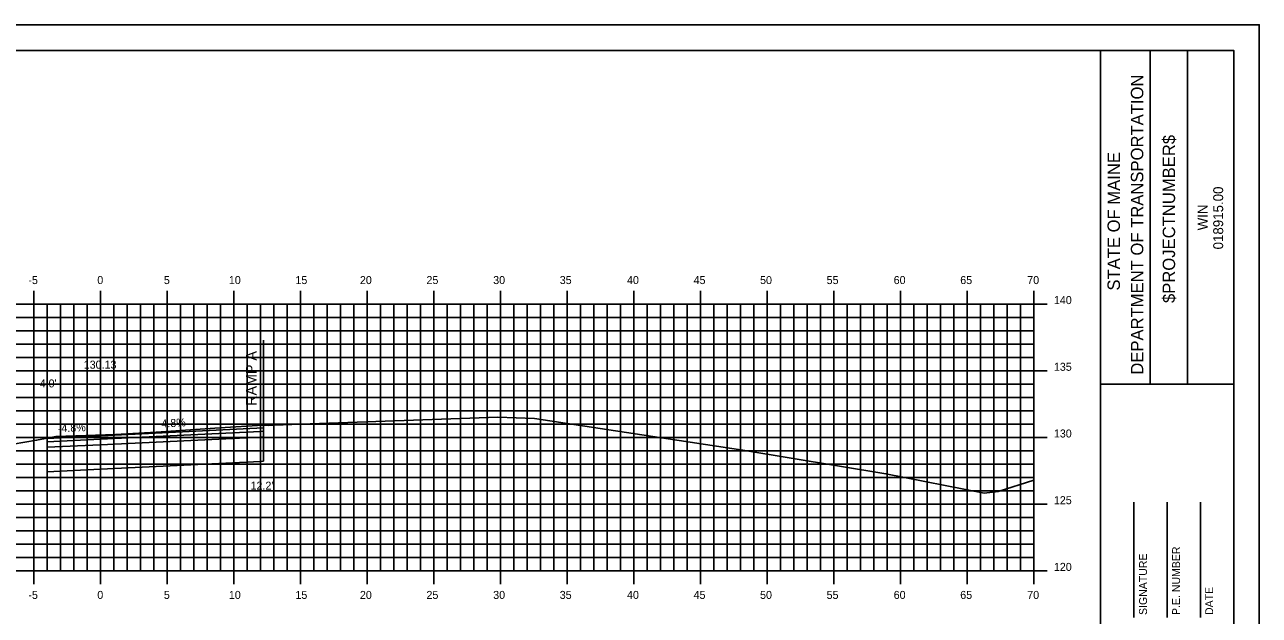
# Model space of a CAD drawing. Extents: x 850851 to 851023, y 365624 to 365734.
# Drawn here: x 850928.8 to 851021.4, y 365689.7 to 365734 of the extents above; entities that cross this region are included whole.
import ezdxf

# ---------------------------------------------------------------- set-up
doc = ezdxf.new("R2010")
doc.units = 0
for name, color, linetype in [('ANNOTATION', 7, 'Continuous'), ('BORDER', 7, 'Continuous'), ('D_Roadway_Centerline', 7, 'Continuous'), ('D_Roadway_Centerline_Text', 7, 'Continuous'), ('D_Roadway_Edge_Shoulder', 7, 'Continuous'), ('D_Roadway_Pavement', 7, 'Continuous'), ('D_Roadway_SubGrade', 7, 'Continuous'), ('D_Text_Standard', 7, 'Continuous'), ('H_V ANNOTATION', 7, 'Continuous'), ('M_Roadway_Centerline', 7, 'Continuous'), ('MAJOR', 7, 'Continuous'), ('MINOR', 7, 'Continuous'), ('PLOT BOUNDARY', 7, 'Continuous'), ('S_Roadway_Centerline', 7, 'Continuous')]:
    doc.layers.add(name, color=color, linetype=linetype)

msp = doc.modelspace()

# ---------------------------------------------------------------- linework, layer by layer
at = {"layer": 'BORDER'}
for p, q in [((851009.496, 365627.027), (851009.496, 365732.027)), ((851013.225, 365707.024), (851013.225, 365732.024)), ((851016.02, 365707.024), (851016.02, 365732.024)), ((851009.497, 365707.021), (851019.496, 365707.021)), ((851011.996, 365689.53), (851011.996, 365698.177)), ((851014.496, 365689.53), (851014.496, 365698.177)), ((851016.996, 365689.53), (851016.996, 365698.177))]:
    msp.add_line(p, q, dxfattribs=at)
msp.add_lwpolyline([(850859.496, 365627.027), (851019.496, 365627.027), (851019.496, 365732.027), (850859.496, 365732.027)], close=True, dxfattribs=at)
at = {"layer": 'D_Roadway_Edge_Shoulder'}
for p, q in [((850946.708, 365703.74), (850930.496, 365702.962)), ((850946.496, 365703.73), (850946.496, 365703.48)), ((850934.494, 365702.904), (850934.496, 365703.154))]:
    msp.add_line(p, q, dxfattribs=at)
at = {"layer": 'D_Roadway_Pavement'}
for points in [[(850934.494, 365702.904), (850930.494, 365702.712), (850930.494, 365702.295), (850934.494, 365702.487)], [(850934.494, 365702.904), (850946.494, 365703.48), (850946.494, 365703.063), (850934.494, 365702.487)]]:
    msp.add_lwpolyline(points, close=True, dxfattribs=at)
msp.add_lwpolyline([(850946.708, 365703.073), (850946.494, 365703.063), (850946.494, 365703.48), (850946.708, 365703.49)], dxfattribs=at)
at = {"layer": 'D_Roadway_SubGrade'}
for p, q in [((850946.708, 365710.321), (850946.708, 365703.574)), ((850946.708, 365703.574), (850946.708, 365701.24))]:
    msp.add_line(p, q, dxfattribs=at)
for points in [[(850934.494, 365702.487), (850930.494, 365702.295), (850930.494, 365702.795), (850930.494, 365702.962), (850930.494, 365700.462), (850934.494, 365700.654)], [(850934.494, 365702.487), (850946.494, 365703.063), (850946.494, 365701.23), (850934.494, 365700.654)]]:
    msp.add_lwpolyline(points, close=True, dxfattribs=at)
msp.add_lwpolyline([(850946.708, 365701.24), (850946.494, 365701.23), (850946.494, 365703.063), (850946.708, 365703.073)], dxfattribs=at)
at = {"layer": 'MAJOR'}
for p, q in [((850929.496, 365714.029), (850929.496, 365713.027)), ((850934.496, 365714.029), (850934.496, 365713.027)), ((850939.496, 365714.029), (850939.496, 365713.027)), ((850944.496, 365714.029), (850944.496, 365713.027)), ((850949.496, 365714.029), (850949.496, 365713.027)), ((850954.496, 365714.029), (850954.496, 365713.027)), ((850959.496, 365714.029), (850959.496, 365713.027)), ((850964.496, 365714.029), (850964.496, 365713.027)), ((850969.496, 365714.029), (850969.496, 365713.027)), ((850974.496, 365714.029), (850974.496, 365713.027)), ((850979.496, 365714.029), (850979.496, 365713.027)), ((850984.496, 365714.029), (850984.496, 365713.027)), ((850989.496, 365714.029), (850989.496, 365713.027)), ((850994.496, 365714.029), (850994.496, 365713.027)), ((850999.496, 365714.029), (850999.496, 365713.027)), ((851004.496, 365714.029), (851004.496, 365713.027)), ((850864.496, 365713.027), (851004.496, 365713.027)), ((850864.496, 365713.027), (851004.496, 365713.027)), ((850929.496, 365693.027), (850929.496, 365713.027)), ((850934.496, 365693.027), (850934.496, 365713.027)), ((850939.496, 365693.027), (850939.496, 365713.027)), ((850944.496, 365693.027), (850944.496, 365713.027)), ((850949.496, 365693.027), (850949.496, 365713.027)), ((850954.496, 365693.027), (850954.496, 365713.027)), ((850959.496, 365693.027), (850959.496, 365713.027)), ((850964.496, 365693.027), (850964.496, 365713.027)), ((850969.496, 365693.027), (850969.496, 365713.027)), ((850974.496, 365693.027), (850974.496, 365713.027)), ((850979.496, 365693.027), (850979.496, 365713.027)), ((850984.496, 365693.027), (850984.496, 365713.027)), ((850989.496, 365693.027), (850989.496, 365713.027)), ((850994.496, 365693.027), (850994.496, 365713.027)), ((850999.496, 365693.027), (850999.496, 365713.027)), ((851005.498, 365713.027), (851003.494, 365713.027)), ((851004.496, 365693.027), (851004.496, 365713.027)), ((851004.496, 365693.027), (851004.496, 365713.027)), ((850864.496, 365708.027), (851004.496, 365708.027)), ((851005.498, 365708.027), (851003.494, 365708.027)), ((850864.496, 365703.027), (851004.496, 365703.027)), ((851005.498, 365703.027), (851003.494, 365703.027)), ((850864.496, 365698.027), (851004.496, 365698.027)), ((851005.498, 365698.027), (851003.494, 365698.027)), ((850864.496, 365693.027), (851004.496, 365693.027)), ((850864.496, 365693.027), (851004.496, 365693.027)), ((850929.496, 365692.025), (850929.496, 365693.027)), ((850934.496, 365692.025), (850934.496, 365693.027)), ((850939.496, 365692.025), (850939.496, 365693.027)), ((850944.496, 365692.025), (850944.496, 365693.027)), ((850949.496, 365692.025), (850949.496, 365693.027)), ((850954.496, 365692.025), (850954.496, 365693.027)), ((850959.496, 365692.025), (850959.496, 365693.027)), ((850964.496, 365692.025), (850964.496, 365693.027)), ((850969.496, 365692.025), (850969.496, 365693.027)), ((850974.496, 365692.025), (850974.496, 365693.027)), ((850979.496, 365692.025), (850979.496, 365693.027)), ((850984.496, 365692.025), (850984.496, 365693.027)), ((850989.496, 365692.025), (850989.496, 365693.027)), ((850994.496, 365692.025), (850994.496, 365693.027)), ((850999.496, 365692.025), (850999.496, 365693.027)), ((851005.498, 365693.027), (851003.494, 365693.027)), ((851004.496, 365692.025), (851004.496, 365693.027))]:
    msp.add_line(p, q, dxfattribs=at)
at = {"layer": 'MINOR'}
for p, q in [((850930.496, 365693.027), (850930.496, 365713.027)), ((850931.496, 365693.027), (850931.496, 365713.027)), ((850932.496, 365693.027), (850932.496, 365713.027)), ((850933.496, 365693.027), (850933.496, 365713.027)), ((850935.496, 365693.027), (850935.496, 365713.027)), ((850936.496, 365693.027), (850936.496, 365713.027)), ((850937.496, 365693.027), (850937.496, 365713.027)), ((850938.496, 365693.027), (850938.496, 365713.027)), ((850940.496, 365693.027), (850940.496, 365713.027)), ((850941.496, 365693.027), (850941.496, 365713.027)), ((850942.496, 365693.027), (850942.496, 365713.027)), ((850943.496, 365693.027), (850943.496, 365713.027)), ((850945.496, 365693.027), (850945.496, 365713.027)), ((850946.496, 365693.027), (850946.496, 365713.027)), ((850947.496, 365693.027), (850947.496, 365713.027)), ((850948.496, 365693.027), (850948.496, 365713.027)), ((850950.496, 365693.027), (850950.496, 365713.027)), ((850951.496, 365693.027), (850951.496, 365713.027)), ((850952.496, 365693.027), (850952.496, 365713.027)), ((850953.496, 365693.027), (850953.496, 365713.027)), ((850955.496, 365693.027), (850955.496, 365713.027)), ((850956.496, 365693.027), (850956.496, 365713.027)), ((850957.496, 365693.027), (850957.496, 365713.027)), ((850958.496, 365693.027), (850958.496, 365713.027)), ((850960.496, 365693.027), (850960.496, 365713.027)), ((850961.496, 365693.027), (850961.496, 365713.027)), ((850962.496, 365693.027), (850962.496, 365713.027)), ((850963.496, 365693.027), (850963.496, 365713.027)), ((850965.496, 365693.027), (850965.496, 365713.027)), ((850966.496, 365693.027), (850966.496, 365713.027)), ((850967.496, 365693.027), (850967.496, 365713.027)), ((850968.496, 365693.027), (850968.496, 365713.027)), ((850970.496, 365693.027), (850970.496, 365713.027)), ((850971.496, 365693.027), (850971.496, 365713.027)), ((850972.496, 365693.027), (850972.496, 365713.027)), ((850973.496, 365693.027), (850973.496, 365713.027)), ((850975.496, 365693.027), (850975.496, 365713.027)), ((850976.496, 365693.027), (850976.496, 365713.027)), ((850977.496, 365693.027), (850977.496, 365713.027)), ((850978.496, 365693.027), (850978.496, 365713.027)), ((850980.496, 365693.027), (850980.496, 365713.027)), ((850981.496, 365693.027), (850981.496, 365713.027)), ((850982.496, 365693.027), (850982.496, 365713.027)), ((850983.496, 365693.027), (850983.496, 365713.027)), ((850985.496, 365693.027), (850985.496, 365713.027)), ((850986.496, 365693.027), (850986.496, 365713.027)), ((850987.496, 365693.027), (850987.496, 365713.027)), ((850988.496, 365693.027), (850988.496, 365713.027)), ((850990.496, 365693.027), (850990.496, 365713.027)), ((850991.496, 365693.027), (850991.496, 365713.027)), ((850992.496, 365693.027), (850992.496, 365713.027)), ((850993.496, 365693.027), (850993.496, 365713.027)), ((850995.496, 365693.027), (850995.496, 365713.027)), ((850996.496, 365693.027), (850996.496, 365713.027)), ((850997.496, 365693.027), (850997.496, 365713.027)), ((850998.496, 365693.027), (850998.496, 365713.027)), ((851000.496, 365693.027), (851000.496, 365713.027)), ((851001.496, 365693.027), (851001.496, 365713.027)), ((851002.496, 365693.027), (851002.496, 365713.027)), ((851003.496, 365693.027), (851003.496, 365713.027)), ((850864.496, 365712.027), (851004.496, 365712.027)), ((851004.496, 365712.027), (851003.494, 365712.027)), ((850864.496, 365711.027), (851004.496, 365711.027)), ((851004.496, 365711.027), (851003.494, 365711.027)), ((850864.496, 365710.027), (851004.496, 365710.027)), ((851004.496, 365710.027), (851003.494, 365710.027)), ((850864.496, 365709.027), (851004.496, 365709.027)), ((851004.496, 365709.027), (851003.494, 365709.027)), ((850864.496, 365707.027), (851004.496, 365707.027)), ((851004.496, 365707.027), (851003.494, 365707.027)), ((850864.496, 365706.027), (851004.496, 365706.027)), ((851004.496, 365706.027), (851003.494, 365706.027)), ((850864.496, 365705.027), (851004.496, 365705.027)), ((851004.496, 365705.027), (851003.494, 365705.027)), ((850864.496, 365704.027), (851004.496, 365704.027)), ((851004.496, 365704.027), (851003.494, 365704.027)), ((850864.496, 365702.027), (851004.496, 365702.027)), ((851004.496, 365702.027), (851003.494, 365702.027)), ((850864.496, 365701.027), (851004.496, 365701.027)), ((851004.496, 365701.027), (851003.494, 365701.027)), ((850864.496, 365700.027), (851004.496, 365700.027)), ((851004.496, 365700.027), (851003.494, 365700.027)), ((850864.496, 365699.027), (851004.496, 365699.027)), ((851004.496, 365699.027), (851003.494, 365699.027)), ((850864.496, 365697.027), (851004.496, 365697.027)), ((851004.496, 365697.027), (851003.494, 365697.027)), ((850864.496, 365696.027), (851004.496, 365696.027)), ((851004.496, 365696.027), (851003.494, 365696.027)), ((850864.496, 365695.027), (851004.496, 365695.027)), ((851004.496, 365695.027), (851003.494, 365695.027)), ((850864.496, 365694.027), (851004.496, 365694.027)), ((851004.496, 365694.027), (851003.494, 365694.027))]:
    msp.add_line(p, q, dxfattribs=at)
at = {"layer": 'PLOT BOUNDARY'}
msp.add_lwpolyline([(850851.403, 365623.968), (851021.403, 365623.968), (851021.403, 365733.968), (850851.403, 365733.968)], close=True, dxfattribs=at)
at = {"layer": 'S_Roadway_Centerline'}
msp.add_lwpolyline([(850927.954, 365702.525), (850929.707, 365702.822), (850930.363, 365702.948), (850931.153, 365703.097), (850935.618, 365703.249), (850938.671, 365703.424), (850943.448, 365703.741), (850946.664, 365703.958), (850947.092, 365703.925), (850947.513, 365703.943), (850949.519, 365704.023), (850964.303, 365704.538), (850967.043, 365704.457), (850973.116, 365703.525), (850982.667, 365702.078), (850993.395, 365700.308), (851000.779, 365698.861), (851001.813, 365698.976), (851004.496, 365699.832)], dxfattribs=at)

# ---------------------------------------------------------------- texts
at = {"layer": 'ANNOTATION'}
for s, height, rotation, p in [('RAMP A', 0.8, 90, (850946.201, 365705.405)), ('-4.8%', 0.6, 2.74828, (850931.306, 365703.402)), ('4.8%', 0.6, 2.74823, (850939.074, 365703.775))]:
    msp.add_text(s, height=height, rotation=rotation, dxfattribs=at).set_placement(p)
at = {"layer": 'BORDER'}
for s, height, p in [('DEPARTMENT OF TRANSPORTATION', 0.93176, (851012.703, 365707.733)), ('$PROJECTNUMBER$', 0.93176, (851015.088, 365713.106)), ('STATE OF MAINE', 0.93176, (851010.951, 365714.039)), ('018915.00', 0.7453, (851018.692, 365717.125)), ('WIN', 0.7453, (851017.533, 365718.557)), ('P.E. NUMBER', 0.59055, (851015.457, 365689.722)), ('SIGNATURE', 0.5906, (851012.977, 365689.722)), ('DATE', 0.5906, (851017.937, 365689.722))]:
    msp.add_text(s, height=height, rotation=90, dxfattribs=at).set_placement(p)
at = {"layer": 'D_Roadway_Centerline'}
for s, p in [('C', (850934.491, 365703.154)), ('L', (850934.496, 365703.146))]:
    msp.add_text(s, height=0.0146, dxfattribs=at).set_placement(p)
at = {"layer": 'D_Roadway_Centerline_Text'}
msp.add_text('130.13', height=0.6, dxfattribs=at).set_placement((850933.236, 365708.186))
at = {"layer": 'D_Text_Standard'}
for s, p in [("4.0'", (850929.933, 365706.779)), ("12.2'", (850945.748, 365699.114))]:
    msp.add_text(s, height=0.6, dxfattribs=at).set_placement(p)
at = {"layer": 'H_V ANNOTATION'}
for s, p in [('-5', (850929.087, 365714.527)), ('0', (850934.255, 365714.527)), ('5', (850939.247, 365714.527)), ('10', (850944.121, 365714.527)), ('15', (850949.113, 365714.527)), ('20', (850953.95, 365714.527)), ('25', (850958.942, 365714.527)), ('30', (850963.945, 365714.527)), ('35', (850968.937, 365714.527)), ('40', (850973.982, 365714.527)), ('45', (850978.974, 365714.527)), ('50', (850983.961, 365714.527)), ('55', (850988.953, 365714.527)), ('60', (850993.982, 365714.527)), ('65', (850998.974, 365714.527)), ('70', (851003.998, 365714.527)), ('140', (851005.996, 365713.027)), ('135', (851005.996, 365708.027)), ('130', (851005.996, 365703.027)), ('125', (851005.996, 365698.027)), ('120', (851005.996, 365693.027)), ('-5', (850929.087, 365690.927)), ('0', (850934.255, 365690.927)), ('5', (850939.247, 365690.927)), ('10', (850944.121, 365690.927)), ('15', (850949.113, 365690.927)), ('20', (850953.95, 365690.927)), ('25', (850958.942, 365690.927)), ('30', (850963.945, 365690.927)), ('35', (850968.937, 365690.927)), ('40', (850973.982, 365690.927)), ('45', (850978.974, 365690.927)), ('50', (850983.961, 365690.927)), ('55', (850988.953, 365690.927)), ('60', (850993.982, 365690.927)), ('65', (850998.974, 365690.927)), ('70', (851003.998, 365690.927))]:
    msp.add_text(s, height=0.6, dxfattribs=at).set_placement(p)
at = {"layer": 'M_Roadway_Centerline'}
for s, p in [('C', (850946.659, 365703.958)), ('L', (850946.664, 365703.951))]:
    msp.add_text(s, height=0.0146, dxfattribs=at).set_placement(p)

doc.saveas('drawing.dxf')
